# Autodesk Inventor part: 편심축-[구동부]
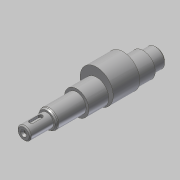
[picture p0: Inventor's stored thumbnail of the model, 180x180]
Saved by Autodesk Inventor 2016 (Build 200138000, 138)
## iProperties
Created: 2019-01
Part Number: 편심축-[구동부]
Material: 강철, 연강
Document SubType Name: Modeling
Designer: mduedu
Density: 7.86 g/cm^3
Mass: 326.79 g
Surface Area: 90.9817 cm^2
Volume: 41.5764 cm^3
Appearance: 강철
Author: mduedu
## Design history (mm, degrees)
sketch "스케치1"
  geometry: L1 (0, 0)-(21, 0); L2 (21, 0)-(21, 6); L3 (21, 6)-(0, 6); L4 (0, 6)-(0, 0); L5 (21, 0)-(48, 0); L6 (48, 0)-(48, 8.5); L7 (48, 8.5)-(21, 8.5); L8 (21, 8.5)-(21, 0); L9 (48, 0)-(108, 0); L10 (108, 0)-(108, 11); L11 (108, 11)-(48, 11); L12 (48, 11)-(48, 0); L13 (108, 0)-(120, 0); L14 (120, 0)-(120, 8.5); L15 (120, 8.5)-(108, 8.5); L16 (108, 8.5)-(108, 0)
  constraints: 32 end point, 8 parallel, 4 horizontal, 4 perpendicular
  dimensions: "d0" = 120 distance between parallel lines of L14 L4; "d2" = 12 distance of L14.end L15.end; "d3" = 60 distance of L10.end L11.end; "d4" = 99 distance between parallel lines of L8 L14; "d5" = 12 diameter of L3 L1; "d6" = 17 diameter of L7 L5; "d7" = 17 diameter of L15 L13; "d8" = 22 diameter of L11 L9
revolve "회전1" sketch "스케치1" stored, may be unused: angle "d9" = 90 deg
node "작업 평면1"
sketch "스케치2"
  geometry: C1 r 15 at (0, 4); C2 r 11 at (0, 0) reference; 1 further point
  constraints: 1 centre point, 1 tangent, 1 vertical alignment
  dimensions: "d11" = 4 distance of point (0, 0) C1.centre
extrude "돌출1" join sketch "스케치2" distance "d12" = 24; taper "d13" = 0 deg
node "작업 평면2"
sketch "스케치3" dims "d16" = 12
  geometry: L1 (-4.5, 2)-(3.5, 2); L2 (3.5, 2)-(3.5, -2); L3 (3.5, -2)-(-4.5, -2); L4 (-4.5, -2)-(-4.5, 2); L5 (-10.5, 8.5)-(-10.5, -8.5) reference; 3 further points
  constraints: 8 end point, 2 midpoint, 2 parallel, 2 vertical alignment, 1 horizontal, 1 horizontal alignment, 1 perpendicular, 4 other
  dimensions: "d14" = 4 distance between parallel lines of L3 L1; "d17" = 4 dimension on L5
extrude "돌출2" cut sketch "스케치3" distance "d18" = 2.5; taper "d19" = 0 deg
chamfer "모따기1" distance "d20" = 1.82; stored, may be unused: second distance "d21" = 2, angle "d22" = 30 deg
fillet "모깎기1" dims "d23" = 2
hole "구멍2" diameter "d39" = 3.242; stored, may be unused: countersink angle "d43" = 60 deg, drill point angle "d45" = 118 deg; dims "d37" = 10, "d38" = 10, "d40" = 8, "d41" = 5.51, "d42" = 2, "d44" = 10
sketch "스케치5"
  geometry: L1 (0, 0)-(2, 0); L2 (2, 0)-(2, 1.621); L3 (0, 2.776)-(0, 0); L4 (0, 2.776)-(2, 1.621); L5 (10, 1.621)-(0, 1.621) reference
  constraints: 8 end point, 1 horizontal, 1 parallel, 1 perpendicular, 1 point on line
  dimensions: "d46" = 2 distance between parallel lines of L2 L3; "d48" = 30 deg angle of L4 L1
revolve "회전2" sketch "스케치5" stored, may be unused: angle "d50" = 90 deg
chamfer "모따기2" distance "d25" = 1; stored, may be unused: second distance "d26" = 2, angle "d27" = 30 deg
node "솔리드1"
